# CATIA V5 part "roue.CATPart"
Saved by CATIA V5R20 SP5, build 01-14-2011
Part number: roue
Bounding box of the stored display mesh (mm): x -2841.379 to 2841.379, y -1079.388 to 1550, z -2841.444 to 2841.444
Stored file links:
  M:\EU_thinkMotion\IAO_2010\iao\IAO_MMS_Groupe1\Problemes\gduval\Gduval\train d'aterrissage squelette + piece kinematic\roue.CATPart
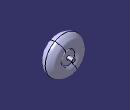
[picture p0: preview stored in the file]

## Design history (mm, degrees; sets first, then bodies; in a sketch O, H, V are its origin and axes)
Body1 (main body)
  Sketch1 on yz-plane, origin (0, 0, 0), H (0, 1, 0), V (0, 0, 1)
    spline S1 through (730, 1105) (925.1862, 1335.1744) (1028.6806, 1507.2954) (1079.3877, 1798.3731) (1067.5673, 1954.729) (926.1953, 2367.3377) (749.7246, 2526.6614) (573.1523, 2655.6684) (340.5615, 2778.4926) (0, 2841.4661)
    spline S2 through (-730, 1105) (-925.1862, 1335.1744) (-1028.6806, 1507.2954) (-1079.3877, 1798.3731) (-1067.5673, 1954.729) (-926.1953, 2367.3377) (-749.7246, 2526.6614) (-573.1523, 2655.6684) (-340.5615, 2778.4926) (0, 2841.4661)
    arc A1 centre (779.292, 1059.9842) radius 66.7542 from (750, 1000) to (730, 1105) ccw
    point P2 (750, 1000)
    point P3 (730, 1105)
    reference projected line E1 (750, 1105) -> (750, -1105) from edge
    point P4 (0, 0)
    point P5 (-730, 1105)
    point P6 (-750, 1000)
    arc A2 centre (-779.292, 1059.9842) radius 66.7542 from (-750, 1000) to (-730, 1105) cw
    construction line L1 (750, 1105) -> (750, -1105)
    line L2 (750, 1000) -> (750, 0)
    point P8 (750, 0)
    line L3 (750, 0) -> (0, 0)
    point P9 (-750, 0)
    point P10 (-750, 1000)
    line L4 (-750, 1000) -> (-750, 0)
    point P11 (0, 0)
    line L5 (-750, 0) -> (0, 0)
    point P12 (730, 1105)
    point P13 (0, 2841.4661)
    point P14 (0, 2841.4661)
    point P15 (-730, 1105)
    point P16 (340.5615, 2778.4926)
    point P17 (-340.5615, 2778.4926)
    point P18 (573.1523, 2655.6684)
    point P19 (-573.1523, 2655.6684)
    point P20 (749.7246, 2526.6614)
    point P21 (-749.7246, 2526.6614)
    point P22 (926.1953, 2367.3377)
    point P23 (-926.1953, 2367.3377)
    point P24 (1067.5673, 1954.729)
    point P25 (-1067.5673, 1954.729)
    point P26 (1079.3877, 1798.3731)
    point P27 (-1079.3877, 1798.3731)
    point P28 (1028.6806, 1507.2954)
    point P29 (-1028.6806, 1507.2954)
    point P30 (925.1862, 1335.1744)
    point P31 (-925.1862, 1335.1744)
    distance P12 L1 = 20
    distance P2 H = 1000
    coincidence: P13 V, P2 E1, P4 H, P4 V, P3 P12, O P11, P13 P14, P15 P5, P6 P10
    symmetry: S1 S2 V, P13 P14 V, P12 P15 V, P16 P17 V, P18 P19 V, P20 P21 V, P22 P23 V, P24 P25 V, P26 P27 V, P28 P29 V, P30 P31 V, P3 P5 V, P2 P6 V, A1 A2 V, P8 P9 V, P2 P10 V, L2 L4 V, O P11 V, L3 L5 V
    tangency: A1 S1
    midpoint: P8 E1
    vertical: L2 V
    horizontal: L3 H
  Shaft1: profile Sketch1, axis Sketch1.L3, angle 360
  Sketch2 on face of Shaft1 from Sketch1.L2, origin (0, 750, 0), H (-1, 0, 0), V (0, 0, 1)
    circle A1 centre (0, 0) radius 260
    radius A1 = 260
  Pad1: profile Sketch2, direction (0, 1, 0), length 800
  Plane1: type Offset, RefPlane end face of Pad1, Offset -430, reversed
